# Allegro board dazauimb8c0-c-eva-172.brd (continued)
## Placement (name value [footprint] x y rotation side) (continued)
D25  *PESD5V0H1BSF  [D-0_6X0_3-0_32H-SMT]  16.57 81.12 270 bottom
D26  *PESD5V0H1BSF  [D-0_6X0_3-0_32H-SMT]  16.57 79.82 90 bottom
D27  *PESD5V0H1BSF  [D-0_6X0_3-0_32H-SMT]  17.74 79.31 270 bottom
D28  *PESD5V0H1BSF  [D-0_6X0_3-0_32H-SMT]  17.74 78.01 90 bottom
D29  *PESD5V0H1BSF  [D-0_6X0_3-0_32H-SMT]  16.57 77.41 270 bottom
D30  *PESD5V0H1BSF  [D-0_6X0_3-0_32H-SMT]  16.57 76.11 90 bottom
D31  *PESD5V0H1BSF  [D-0_6X0_3-0_32H-SMT]  17.74 76.08 270 bottom
D32  *PESD5V0H1BSF  [D-0_6X0_3-0_32H-SMT]  17.74 74.78 90 bottom
D33  RB500V-40  [D-1_85X1_25-2P-0_95H]  103.85 54.09 180 bottom
D34  1N4148WS  [D-SOD323-1_85X1_25-0_95H]  193.2 33.41 270 bottom
D35  1N4148WS  [D-SOD323-1_85X1_25-0_95H]  194.7 33.41 270 bottom
D36  RB500V-40  [D-SOD323-1_85X1_25-0_95H]  201.86 25.16 0 bottom
D37  *RB500V-40  [D-SOD323-1_85X1_25-0_95H]  200.98 23.13 0 bottom
D38  TPC@EGA10402V05AH_0.2p  [R0402]  9.97 18.78 90 bottom
D39  TPC@EGA10402V05AH_0.2p  [R0402]  11.36 18.4 0 bottom
D40  TPC@P4SMAFJ20A  [D-3_8X2_5]  15.1 14.46 270 bottom
D41  TPC@EGA10402V05AH_0.2p  [R0402]  11.62 13.83 0 bottom
D42  BAT54CW  [SOT23-1_7-65-3P]  17.26 9.88 0 bottom
D43  *RB500V-40  [D-1_85X1_25-2P-0_95H]  110.83 48.09 270 bottom
EC1  180p/25V_2  [C0201]  55.43 87.87 0 top
EC2  180p/25V_2  [C0201]  50.73 51.04 180 top
EC3  SSD@10u/6.3V_4  [C0402_2]  22.29 6.97 0 top
EC4  SSD@10u/6.3V_4  [C0402_2]  24.83 5.45 0 top
EC5  SSD@0.1u/16V_2  [C0201]  24.83 4.43 180 top
EC6  PBA@AZ5725-01F.R7G  [ESD-1X0_6-2P]  57.08 22.52 0 bottom
EC7  PBA@AZ5725-01F.R7G  [ESD-1X0_6-2P]  59.02 22.52 0 bottom
EC8  TPC@22u/6.3V_6  [C0603]  11.24 21.63 270 bottom
EC9  *220p/50V_4  [C0402]  180.48 20.1 90 bottom
FAN1  50278-00401-001  [WTB-50278-00401-V01-4P-L]  174.73 29.5 90 bottom
HD1  51625-01201-001  [51625-01201-001-12P-L]  217.53 13.57 270 bottom
HE1  APX8132AI-TRG  [SOT23-2_38-95-3P]  34.9 122.75 90 top
HOLE1  *spad-davidoff-1  [SPAD-DAVIDOFF-1]  43.94 123.9 0 top
HOLE2  *h-c98d98n  [2D-BARCODE-6X6-S]  18.76 109.23 0 top
HOLE3  *h-s157d157n  [H-S157D157N]  110.17 72.38 0 top
HOLE4  *spad-c315np  [SPAD-C315NP]  131.79 64.66 0 top
HOLE5  *spad-re209x315np  [SPAD-RE209X315NP]  215.74 37.1 0 top
HOLE6  *spad-c354np  [SPAD-C354NP]  140.49 22.1 0 top
HOLE7  *spad-c354np  [SPAD-C354NP]  41.2 10 0 top
HOLE8  *H-DAVIDOFF-3  [H-DAVIDOFF-3]  136.2 123.5 180 bottom
HOLE9  *h-c98d98n  [H-C98D98N]  142.5 123.5 180 bottom
HOLE10  EV@H-C256I186D102P2  [H-C256I186D102P2]  90.53 123.23 180 bottom
HOLE11  *hg-o335x315d252x232p2  [HG-O335X315D252X232P2]  11.25 109.2 180 bottom
HOLE12  *SPAD-RE138X197  [SPAD-RE138X197]  3.35 108.2 180 bottom
HOLE13  *h-s157d157n  [2D-BARCODE-6X6-S]  18.02 104.15 0 bottom
HOLE14  *h-tic157bc276d150p2  [H-TIC157BC276D150P2]  71.88 89.73 180 bottom
HOLE15  EV@H-C256I186D102P2  [H-C256I186D102P2]  119.53 84.23 180 bottom
HOLE16  *hg-c354i158d118p2  [HG-C354I158D118P2]  17.48 68.15 180 bottom
HOLE17  *h-tic157bc276d150p2  [H-TIC157BC276D150P2]  106.88 58.74 180 bottom
HOLE18  *HG-C276D126P2  [HG-C276D126P2]  216.55 54 180 bottom
HOLE19  *h-tic157bc276d150p2  [H-TIC157BC276D150P2]  71.88 27.73 180 bottom
HOLE20  *h-c75d75n  [H-C75D75N]  4.2 24 180 bottom
HOLE21  h-davidoff-1  [H-DAVIDOFF-1]  216.8 21.88 180 bottom
HOLE22  *hg-c354i274d220p2  [HG-C354I274D220P2]  86.2 15.5 180 bottom
HOLE23  *H-DAVIDOFF-1-1  [H-DAVIDOFF-1-1]  5.2 4.4 180 bottom
J1  *JUMP  [JOPEN25X30_S]  12 10.02 180 bottom
JDIM1  D4AS0-26010-1P40  [DDR4-D4AR0-26001-1P40-RVS-SMT]  54.35 62.83 270 bottom
L1  EV@HCB1005KF-330T30  [R0402]  88.07 107.3 180 top
L2  EV@HCB1005KF-330T30  [R0402]  88.07 106.29 180 top
L3  *EV@HCB1608KF_300_2A  [R0603]  89.44 102.14 180 top
L4  EV@HCB1005KF-330T30  [R0402]  89.85 100.93 180 top
L5  EV@HCB1005KF-330T30  [R0402]  105.6 99.43 0 top
L6  BLM15AG121SN1D  [R0402]  185.35 32.24 180 top
L7  HCB2012KF-220T60  [R0805]  202.75 31.79 0 top
L8  *Short_0603  [S0603]  49.08 31.43 180 top
L9  BLM15AG121SN1D  [R0402]  200.9 21.04 180 top
L10  BLM15AG121SN1D  [R0402]  202.58 19.75 90 top
L11  BLM15AG601SN1D  [R0402]  41.34 103.62 90 bottom
L12  BLM15AG601SN1D  [R0402]  42.48 103.62 90 bottom
L13  HCB1608KF-121T30  [R0603]  210.73 34.25 0 bottom
L14  PBY160808T-600Y-N  [R0603]  210.93 27.98 0 bottom
L15  HCB1005KF-330T30  [R0402]  72.22 22.34 90 bottom
L16  HCB1005KF-330T30  [R0402]  75.53 22.34 90 bottom
NOREF  -  []  -292.8 -269 0 top
NOREF#2  -  [unnamed#2]  217.23 12.03 0 top
NOREF#3  -  [unnamed#2]  127.37 119.82 0 top
NOREF#4  -  [unnamed#2]  10.3 23 0 top
NOREF#5  -  []  166.94 -30.24 0 top
NOREF#6  -  []  -292.8 -269 0 top
NOREF#7  -  []  107.12 22.34 0 top
NOREF#8  -  []  1.84 -42.94 0 top
NOREF#9  -  [unnamed#2]  119.72 125.46 180 bottom
NOREF#10  -  []  14.67 116.11 180 bottom
NOREF#11  -  [unnamed#2]  212.15 18.58 180 bottom
NOREF#12  -  [unnamed#2]  9.71 9.03 180 bottom
PC1  1u/10V_4  [C0402]  64.04 124.57 90 top
PC2  10u/10V_4  [C0402_2]  65.11 124.57 270 top
PC3  0.1u/25V_4  [C0402]  66.18 124.57 270 top
PC4  *EV@10u/25V_8  [C0805]  74.06 124.55 180 top
PC5  EV@10u/25V_6  [C0603]  74.06 122.52 180 top
PC6  0.047u/50V_6  [C0603]  45.86 122.13 0 top
PC7  *22u/6.3V_6  [C0603]  49.55 122.11 0 top
PC8  1000p/50V_4  [C0402]  44.05 121.73 90 top
PC9  EV@470u/2V_7343H1.9  [CC7343]  80.48 121.42 180 top
PC10  0.1u/25V_4  [C0402]  68.18 121.19 270 top
PC11  10u/25V_6  [C0603]  69.4 120.94 270 top
PC12  10u/25V_6  [C0603]  70.83 124.45 0 top
PC13  EV@10u/25V_6  [C0603]  74.06 120.49 180 top
PC14  2200p/50V_4  [C0402]  12.41 118.43 90 top
PC15  0.47u/10V_4  [C0402]  66.22 118.3 0 top
PC16  10u/6.3V_4  [C0402_2]  61.77 118.15 180 top
PC17  *EV@2200p/50V_4  [C0402]  75.25 118.1 0 top
PC18  10u/6.3V_4  [C0402_2]  63.5 118.09 180 top
PC19  EV@1u/25V_4  [C0402]  68.36 115.35 270 top
PC20  EV@0.22u/10V_4  [C0402]  73.24 115.43 270 top
PC21  EV@0.1u/16V_4  [C0402]  69.56 114.13 270 top
PC22  EV@1500p/50V_4  [C0402]  70.52 113.73 270 top
PC23  EV@0.22u/25V_4  [C0402]  77.61 113.55 270 top
PC24  EV@56p/50V_4  [C0402]  69.23 110.93 0 top
PC25  EV@2.2u/10V_4  [C0402]  78.57 110.91 270 top
PC26  *EV@100p/50V_4  [C0402]  70.65 110.45 270 top
PC27  EV@56p/50V_4  [C0402]  69.23 109.97 0 top
PC28  EV@0.22u/25V_4  [C0402]  77.91 108.44 90 top
PC29  *EV@0.22u/10V_4  [C0402]  72.07 106.67 270 top
PC30  *EV@2200p/50V_4  [C0402]  82.87 106.59 0 top
PC31  EV@10u/6.3V_6  [C0603]  20.64 97.9 0 top
PC32  EV@0.1u/16V_4  [C0402]  20.76 96.63 0 top
PC33  EV@1000p/50V_4  [C0402]  22.54 96.63 270 top
PC34  EV@1000p/50V_4  [C0402]  23.56 96.63 270 top
PC35  EV@10u/6.3V_6  [C0603]  25.59 95.11 180 top
PC36  EV@0.1u/16V_4  [C0402]  25.33 93.84 180 top
PC37  EV@1u/25V_4  [C0402]  25.72 91.3 180 top
PC38  EV@1u/25V_4  [C0402]  21.14 90.16 90 top
PC39  *EV@820p/50V_4  [C0402]  22.16 90.16 90 top
PC40  EV@0.1u/16V_4  [C0402]  23.18 90.16 90 top
PC41  EV@0.1u/16V_4  [C0402]  24.19 90.16 90 top
PC42  *EV@22u/6.3V_6  [C0603]  138.82 77.58 0 top
PC43  EV@0.1u/16V_4  [C0402]  138.01 74.38 90 top
PC44  EV@22u/6.3V_6  [C0603]  140.65 74.38 90 top
PC45  EV@22u/6.3V_6  [C0603]  142.1 74.38 90 top
PC46  EV@22u/6.3V_6  [C0603]  139.23 74.36 90 top
PC47  *EV@0.1u/25V_4  [C0402]  138.87 67.3 180 top
PC48  EV@2200p/50V_4  [C0402]  139.84 64.04 180 top
PC49  0.1u/25V_4  [C0402]  142.31 59.83 180 top
PC50  *22u/6.3V_6  [C0603]  90.38 59.4 0 top
PC51  0.1u/25V_4  [C0402]  139.3 58.7 90 top
PC52  22u/6.3V_6  [C0603]  90.38 57.97 0 top
PC53  330p/50V_4  [C0402]  143.87 56.73 0 top
PC54  22u/6.3V_6  [C0603]  90.56 56.55 0 top
PC55  0.1u/25V_4  [C0402]  134.67 55.49 270 top
PC56  82p/50V_4  [C0402]  143.55 55.37 90 top
PC57  *100p/50V_4  [C0402]  143.55 53.65 90 top
PC58  2.2u/10V_4  [C0402]  134.29 53.12 0 top
PC59  0.1u/25V_4  [C0402]  134.69 51.45 90 top
PC60  0.47u/6.3V_4  [C0402]  144.84 50.28 270 top
PC61  4.7u/6.3V_4  [C0402_2]  143.57 50.15 90 top
PC62  *0.1u/25V_4  [C0402]  138.34 40.82 90 top
PC63  22u/6.3V_6  [C0603]  113.42 38.85 0 top
PC64  22u/6.3V_6  [C0603]  113.42 37.43 0 top
PC65  *22u/6.3V_6  [C0603]  113.42 36 0 top
PC66  22u/6.3V_6  [C0603]  156.48 35.98 270 top
PC67  *22u/6.3V_6  [C0603]  157.9 35.95 270 top
PC68  2200p/50V_4  [C0402]  24.37 35.55 90 top
PC69  *22u/6.3V_6  [C0603]  159.95 35.42 180 top
PC70  10p/50V_4  [C0402]  147.56 35.34 90 top
PC71  0.1u/16V_4  [C0402]  144.84 34.53 180 top
PC72  0.1u/16V_4  [C0402]  157.67 33.92 180 top
PC73  100p/50V_4  [C0402]  138.49 33.51 0 top
PC74  0.1u/50V_4  [C0402]  132.12 32.55 90 top
PC75  *2200p/50V_6  [C0603]  37.15 32.24 270 top
PC76  0.1u/50V_4  [C0402]  133.46 32.14 0 top
PC77  *100p/50V_4  [C0402]  136.84 31.74 180 top
PC78  0.1u/16V_4  [C0402]  18.98 31.71 270 top
PC79  0.1u/16V_4  [C0402]  144.71 31.41 270 top
PC80  2.2u/10V_4  [C0402]  131.61 31.18 180 top
PC81  10u/6.3V_6  [C0603]  20.79 30.92 180 top
PC82  1u/25V_4  [C0402]  22.59 30.75 270 top
PC83  22u/6.3V_6  [C0603]  33.72 30.47 270 top
PC84  *22u/6.3V_6  [C0603]  35.27 30.47 270 top
PC85  10u/6.3V_4  [C0402_2]  44.38 29.2 180 top
PC86  2200p/50V_4  [C0402]  121.6 29.2 90 top
PC87  *0.1u/16V_4  [C0402]  25.23 28.56 180 top
PC88  1u/25V_4  [C0402]  158.05 28.23 180 top
PC89  0.01u/50V_4  [C0402]  44.38 28.05 180 top
PC90  1u/25V_4  [C0402]  152.67 27.82 90 top
PC91  *0.01u/50V_4  [C0402]  120.46 27.8 270 top
PC92  1000p/50V_4  [C0402]  19.37 27.75 0 top
PC93  0.1u/16V_4  [C0402]  25.23 27.6 180 top
PC94  *0.1u/6.3V_2  [C0201]  39.18 27.55 0 top
PC95  0.1u/6.3V_2  [C0201]  37.02 27.42 270 top
PC96  0.01u/50V_4  [C0402]  133.68 27.29 90 top
PC97  22u/6.3V_6  [C0603]  35.11 26.91 90 top
PC98  1000p/50V_4  [C0402]  19.37 26.76 0 top
PC99  *0.1u/16V_4  [C0402]  25.23 26.63 180 top
PC100  *22p/50V_4  [C0402]  39.18 25.92 270 top
PC101  1u/25V_4  [C0402]  25.23 25.67 180 top
PC102  *22p/50V_4  [C0402]  159.35 25.65 90 top
PC103  0.1u/16V_4  [C0402]  22.03 25.01 180 top
PC104  0.47u/6.3V_4  [C0402]  166.64 23.89 270 top
PC105  10u/6.3V_6  [C0603]  22.06 23.79 180 top
PC106  10u/6.3V_6  [C0603]  157.8 23.05 90 top
PC107  10u/6.3V_6  [C0603]  167.83 23 90 top
PC108  0.1u/16V_4  [C0402]  156.42 22.67 90 top
PC109  0.1u/16V_4  [C0402]  153.45 22.64 90 top
PC110  1000p/50V_4  [C0402]  154.42 22.64 90 top
PC111  1000p/50V_4  [C0402]  155.46 22.64 90 top
PC112  10u/6.3V_6  [C0603]  152.26 22.47 90 top
PC113  22u/6.3V_6  [C0603]  33.49 22.08 270 top
PC114  *22u/6.3V_6  [C0603]  34.96 22.06 270 top
PC115  *680p/50V_6  [C0603]  42.73 20.56 180 top
PC116  0.1u/25V_4  [C0402]  39.18 18.91 270 top
PC117  2200p/50V_4  [C0402]  100.54 17.31 90 top
PC118  0.1u/50V_4  [C0402]  101.92 17.26 90 top
PC119  22u/6.3V_6  [C0603]  34.99 15.99 90 top
PC120  *22u/6.3V_6  [C0603]  36.49 15.99 90 top
PC121  22u/6.3V_6  [C0603]  38.16 15.99 90 top
PC122  *47p/50V_4  [C0402]  107.63 15.87 270 top
PC123  *47p/50V_4  [C0402]  100.52 15.11 270 top
PC124  EV@0.1u/25V_4  [C0402]  69.44 125.46 0 bottom
PC125  *1u/10V_4  [C0402]  64.78 124.67 90 bottom
PC126  *1u/10V_4  [C0402]  67.22 124.53 90 bottom
PC127  EV@2200p/50V_4  [C0402]  69.44 124.5 0 bottom
PC128  *22u/6.3V_6  [C0603]  60.79 124.5 90 bottom
PC129  22u/6.3V_6  [C0603]  62.2 124.5 90 bottom
PC130  22u/6.3V_6  [C0603]  53.64 124.36 270 bottom
PC131  22u/6.3V_6  [C0603]  52.08 124.35 270 bottom
PC132  22u/6.3V_6  [C0603]  55.22 124.34 270 bottom
PC133  22u/6.3V_6  [C0603]  56.73 124.34 270 bottom
PC134  *EV@15u/25V_3528H1.9  [C3528]  73.47 124.07 180 bottom
PC135  EV@470u/2V_7343H1.9  [CC7343]  110.25 123.56 180 bottom
PC136  *680p/50V_6  [C0603]  63.65 122.45 180 bottom
PC137  22u/6.3V_6  [C0603]  49.55 122.11 0 bottom
PC138  2200p/50V_4  [C0402]  67.22 121.19 90 top
PC139  0.1u/25V_4  [C0402]  60.01 121.19 270 bottom
PC140  10u/25V_6  [C0603]  70.83 122.97 0 top
PC141  EV@22U/6.3V_6  [C0603]  103.72 120.59 0 bottom
PC142  *10u/6.3V_4  [C0402_2]  64 119.67 180 bottom
PC143  0.1u/50V_4  [C0402]  40.07 117.82 0 bottom
PC144  EV@22U/6.3V_6  [C0603]  87.69 117.74 180 bottom
PC145  0.1u/50V_4  [C0402]  40.07 116.85 0 bottom
PC146  EV@4700p/25V_4  [C0402]  74.48 112.66 90 bottom
PC147  *EV@56p/50V_4  [C0402]  73.37 108.62 270 bottom
PC148  EV@2200p/50V_4  [C0402]  77.51 106.01 270 bottom
PC149  EV@0.1u/25V_4  [C0402]  78.5 106.01 270 bottom
PC150  EV@470u/2V_7343H1.9  [CC7343]  86.88 104.53 270 bottom
PC151  EV@0.1u/16V_4  [C0402]  75.17 102.35 180 bottom
PC152  EV@10u/25V_8  [C0805]  79.51 101.46 90 bottom
PC153  EV@10u/25V_8  [C0805]  81.49 101.46 90 bottom
PC154  *EV@10u/25V_8  [C0805]  83.48 101.46 90 bottom
PC155  EV@10u/6.3V_6  [C0603]  69.66 100.04 0 bottom
PC156  EV@0.1u/16V_4  [C0402]  71.94 99.43 180 bottom
PC157  EV@10u/6.3V_6  [C0603]  69.66 98.61 0 bottom
PC158  *EV@0.1u/16V_4  [C0402]  75.37 95.87 90 bottom
PC159  EV@0.1u/16V_4  [C0402]  66.05 95.36 270 bottom
PC160  EV@10u/6.3V_6  [C0603]  64.86 94.25 270 bottom
PC161  EV@0.01u/50V_4  [C0402]  74.86 94.22 180 bottom
PC162  *22u/6.3V_6  [C0603]  115.14 80.61 270 bottom
PC163  330u/2.5V_7343H1.9  [CC7343]  111.94 80.22 90 bottom
PC164  *330u/2.5V_7343H1.9  [CC7343]  118.54 75.09 90 bottom
PC165  *330u/2.5V_7343H1.9  [CC7343]  123.34 75.09 90 bottom
PC166  *330u/2.5V_7343H1.9  [CC7343]  128.04 75.09 90 bottom
PC167  *EV@22u/6.3V_6  [C0603]  140.65 74.38 90 bottom
PC168  EV@22u/6.3V_6  [C0603]  142.1 74.38 90 bottom
PC169  EV@22u/6.3V_6  [C0603]  139.23 74.36 90 bottom
PC170  EV@10u/6.3V_6  [C0603]  141.59 72.07 180 bottom
PC171  EV@0.1u/25V_4  [C0402]  137.98 70.34 180 bottom
PC172  *EV@680p/50V_6  [C0603]  131.57 69.62 0 bottom
PC173  0.1u/25V_4  [C0402]  127.68 69.54 0 bottom
PC174  0.1u/25V_4  [C0402]  129.4 69.54 180 bottom
PC175  EV@0.01u/6.3V_2  [C0201]  140.98 69.46 0 bottom
PC176  *22u/6.3V_6  [C0603]  102.88 68.36 270 bottom
PC177  10u/25V_8  [C0805]  127.99 68.07 0 bottom
PC178  EV@0.22u/10V_4  [C0402]  141.87 67.96 180 bottom
PC179  22u/6.3V_6  [C0603]  104.3 66.89 270 bottom
PC180  *15u/25V_3528H1.9  [C3528]  132.44 66.32 270 bottom
PC181  *10u/25V_8  [C0805]  128.16 66.1 0 bottom
PC182  2200p/50V_4  [C0402]  130.26 65.98 90 bottom
PC183  *EV@1000p/50V_4  [C0402]  141.46 64.88 180 bottom
PC184  EV@10u/25V_6  [C0603]  135.77 62.78 0 bottom
PC185  *EV@0.01u/50V_4  [C0402]  139.69 62.11 180 bottom
PC186  0.1u/25V_4  [C0402]  140.75 60.66 270 bottom
PC187  0.1u/25V_4  [C0402]  141.71 60.66 270 bottom
PC188  *2200p/25V_2  [C0201]  124.2 58.95 180 bottom
PC189  10u/25V_8  [C0805]  128.86 58.55 0 bottom
PC190  2200p/50V_4  [C0402]  128.53 56.97 180 bottom
PC191  0.22u/25V_4  [C0402]  139.16 55.93 270 bottom
PC192  *0.1u/6.3V_2  [C0201]  138.1 55.85 90 bottom
PC193  0.1u/25V_4  [C0402]  134.75 55.59 90 bottom
PC194  *2200p/25V_2  [C0201]  124.23 55.56 180 bottom
PC195  *100p/50V_4  [C0402]  141.44 55.53 0 bottom
PC196  10u/25V_8  [C0805]  128.85 55.4 0 bottom
PC197  10u/25V_8  [C0805]  132.66 54.62 180 bottom
PC198  *100p/50V_4  [C0402]  141.44 54.57 0 bottom
PC199  *0.1u/6.3V_2  [C0201]  141.67 52.64 270 bottom
PC200  0.1u/6.3V_2  [C0201]  137.86 52.06 180 bottom
PC201  *22u/6.3V_6  [C0603]  113.66 51.44 0 bottom
PC202  *10u/25V_8  [C0805]  132.66 51.23 180 bottom
PC203  *22u/6.3V_6  [C0603]  113.65 49.95 0 bottom
PC204  10u/25V_8  [C0805]  132.88 49.26 180 bottom
PC205  0.1u/25V_4  [C0402]  132.14 47.79 180 bottom
PC206  *2200p/25V_2  [C0201]  126.54 47.78 180 bottom
PC207  10u/25V_8  [C0805]  130.28 47.35 90 bottom
PC208  22u/6.3V_6  [C0603]  112.48 46.57 270 bottom
PC209  *0.1u/16V_4  [C0402]  139.81 46.17 90 bottom
PC210  1u/6.3V_4  [C0402]  135.36 45.16 0 bottom
PC211  0.1u/25V_4  [C0402]  141.95 44.47 0 bottom
PC212  *22u/6.3V_6  [C0603]  111.94 43.27 90 bottom
PC213  2200p/50V_4  [C0402]  141.95 40.83 180 bottom
PC214  0.1u/25V_4  [C0402]  134.31 40.33 90 bottom
PC215  *10u/25V_8  [C0805]  130.87 40.03 270 bottom
PC216  10u/25V_8  [C0805]  132.84 40.03 270 bottom
PC217  27p/50V_4  [C0402]  141.09 39.47 90 bottom
PC218  330u/2.5V_7343H1.9  [CC7343]  118.11 38.17 0 bottom
PC219  *22u/6.3V_6  [C0603]  112.02 38.14 0 bottom
PC220  *470p/50V_4  [C0402]  141.44 38.11 0 bottom
PC221  2200p/50V_4  [C0402]  142.81 37.32 90 bottom
PC222  10u/25V_8  [C0805]  129.47 36.24 90 bottom
PC223  10u/25V_8  [C0805]  131.44 36.23 90 bottom
PC224  22u/6.3V_6  [C0603]  156.55 36.03 270 bottom
PC225  22u/6.3V_6  [C0603]  157.97 36.03 270 bottom
PC226  22u/6.3V_6  [C0603]  160.01 35.62 180 bottom
PC227  4.7u/6.3V_4  [C0402_2]  144.84 35.55 0 bottom
PC228  0.1u/25V_4  [C0402]  133.26 35.52 90 bottom
PC229  0.1u/25V_4  [C0402]  148.02 35.42 90 bottom
PC230  2200p/50V_4  [C0402]  120.74 35.33 180 bottom
PC231  0.1u/16V_4  [C0402]  118.32 35.3 180 bottom
PC232  0.1u/25V_4  [C0402]  122.09 34.94 90 bottom
PC233  10u/25V_8  [C0805]  140.65 34.48 0 bottom
PC234  1u/10V_4  [C0402]  144.51 34.43 0 bottom
PC235  100p/50V_4  [C0402]  137.98 33.49 0 bottom
PC236  2200p/50V_4  [C0402]  111.01 33.46 180 bottom
PC237  0.1u/50V_4  [C0402]  131.99 33.21 0 bottom
PC238  0.47u/25V_6  [C0603]  129.81 33.06 0 bottom
PC239  10u/25V_6  [C0603]  140.78 32.75 0 bottom
PC240  10u/25V_8  [C0805]  127.39 32.19 90 bottom
PC241  22u/25V_8  [C0805]  111.57 31.96 180 bottom
PC242  *0.1u/16V_4  [C0402]  138.64 31.66 270 bottom
PC243  0.047u/50V_6  [C0603]  129.78 31.23 0 bottom
PC244  0.1u/25V_4  [C0402]  141.41 30.59 270 bottom
PC245  0.1u/25V_4  [C0402]  142.43 30.59 90 bottom
PC246  22u/25V_8  [C0805]  111.57 29.96 180 bottom
PC247  *680p/50V_6  [C0603]  144.71 28.84 0 bottom
PC248  0.1u/25V_4  [C0402]  129.35 28.59 180 bottom
PC249  *680p/50V_6  [C0603]  127.6 28.31 270 bottom
PC250  *0.1u/16V_4  [C0402]  153.38 27.49 90 bottom
PC251  0.1u/16V_4  [C0402]  155.31 27.49 90 bottom
PC252  *0.1u/16V_4  [C0402]  156.27 27.49 90 bottom
PC253  0.1u/25V_4  [C0402]  129.02 27.24 270 bottom
PC254  0.1u/25V_4  [C0402]  129.98 27.24 270 bottom
PC255  0.1u/16V_4  [C0402]  103.31 26.63 90 bottom
PC256  0.1u/50V_4  [C0402]  94.12 24.12 180 bottom
PC257  4.7u/6.3V_4  [C0402_2]  159.32 23.23 270 bottom
PC258  *100p/50V_4  [C0402]  94.12 23.09 0 bottom
PC259  10u/6.3V_6  [C0603]  169.99 22.72 180 bottom
PC260  0.1u/16V_4  [C0402]  168.13 22.57 90 bottom
PC261  2200p/50V_4  [C0402]  47.33 20.31 180 bottom
PC262  0.1u/25V_4  [C0402]  46.8 18.96 270 bottom
PC263  0.1u/25V_4  [C0402]  47.79 18.96 90 bottom
PC264  10u/25V_8  [C0805]  49.26 17.94 270 bottom
PC265  1u/10V_4  [C0402]  42.91 16.17 0 bottom
PC266  4.7u/10V_4  [C0402_2]  41.34 15.91 90 bottom
PC267  0.1u/16V_4  [C0402]  42.91 15.19 0 bottom
PC268  0.1u/16V_4  [C0402]  33.46 15.1 0 bottom
PC269  22u/6.3V_6  [C0603]  35.88 15.1 180 bottom
PC270  10u/25V_8  [C0805]  50.68 14.26 90 bottom
PC271  0.1u/16V_4  [C0402]  46.67 14.21 180 bottom
PC272  10p/50V_4  [C0402]  44.38 13.37 180 bottom
PD1  *EV@RB500V-40  [D-SOD323-1_85X1_25-0_95H]  76.64 115.66 180 top
PD2  P4SMAFJ20A  [D-3_8X2_5]  16.06 115.3 180 top
PD3  BAT54CW  [SOT23-1_7-65-3P]  109.59 40.6 270 top
PD4  BAT54CW  [SOT23-1_7-65-3P]  126.76 31.84 180 top
PD5  PDZ5.6B  [D-SOD323-1_7X1_25-PMEG4005AEA]  109.03 16.58 90 top
PD6  PDZ5.6B  [D-SOD323-1_7X1_25-PMEG4005AEA]  99.25 15.82 90 top
PD7  EV@1SS355  [D-SOD323-1_85X1_25-0_95H]  73.09 96.13 90 bottom
PJ2  *short3720  [SHORT3720]  154.37 31.1 180 top
PJ3  *short3720  [SHORT3720]  31.05 29.96 270 top
PJ4  *short3720  [SHORT3720]  32.45 18.53 90 top
PJ6  30706-00042-001  [DCJK-30706-00042-001-3P-SMT]  1.85 116.6 90 bottom
PJ7  *short3720  [SHORT3720]  70.39 102.98 270 bottom
PJ8  *short3720  [SHORT3720]  140.65 78.6 180 bottom
PJ10  *short3720  [SHORT3720]  135.62 37.3 270 bottom
PJ11  50458-00801-V02  [WTB-50458-00801-V02-8P-L]  102.45 16.42 180 bottom
PL1  4.7uH/1.08A_2.5x2.0x1.2  [L2_5X2-1_2]  61.86 124.65 180 top
PL2  0.68uH/15.5A_7x7x3  [L6_6X6_6-2_8H]  55.56 122.37 180 top
PL3  1uH/3.35A_2.5x2.0x1.2  [L2_5X2-1_2H]  37.6 29.58 180 top
PL4  EV@0.22uH/23A_7x7x3  [L6_6X6_6-3H]  81.55 120.31 0 bottom
PL5  EV@0.22uH/23A_7x7x3  [L6_6X6_6-3H]  84.62 113.19 0 bottom
PL6  EV@0.68uH/15.5A_7x7x3  [L6_6X6_6-3H]  134.96 74.43 90 bottom
PL7  0.24uH/28A_7x7x3  [L6_6X6_6-2_8H]  119.31 62.97 180 bottom
PL8  0.24uH/28A_7x7x3  [L6_6X6_6-2_8H]  119.84 51.52 180 bottom
PL9  0.22uH/23A_7x7x3  [L6_6X6_6-2_8H]  117.86 44.22 180 bottom
PL10  1uH/11A_7x7x3  [L6_6X6_6-2_8H]  152.21 32.12 0 bottom
PL11  6.8uH/4.5A_7x7x3  [L6_6X6_6-2_8H]  117.82 29.07 180 bottom
PL12  2.2uH/1.67A_2.5x2.0x1.2  [L2_5X2-1_2H]  166.05 22.97 0 bottom
PL13  1uH/11A_7x7x3  [L6_6X6_6-2_8H]  37.07 19.42 180 bottom
PQ1  EV@LTC044EUBFS8TL  [SOT23-1_7-65-3P]  122.87 122.8 0 top
PQ2  EV@2N7002KW  [SOT23-1_7-65-3P]  123.76 119.87 90 top
PQ3  AONS32314  [POWER-5_2X5_55-1_27-5P]  40.12 119.49 0 top
PQ4  AONS32314  [POWER-5_2X5_55-1_27-5P]  46.98 118.05 180 top
PQ5  EV@2N7002K  [SOT23-2-95-3P]  135.8 77.91 180 top
PQ6  EV@DMG1012T-7  [SOT23-1_38-5-3P]  131.91 77.13 270 top
PQ7  DDTC144EUA-7-F  [SOT23-1_7-65-3P]  24.57 40.47 90 top
PQ8  2N7002K  [SOT23-2-95-3P]  27.49 37.63 90 top
PQ9  2N7002KW  [SOT23-1_7-65-3P]  136.92 35.43 180 top
PQ10  AOSS32334C  [SOT23-2_38-95-3P]  26.76 34.15 180 top
PQ11  AONS32314  [POWER-5_2X5_55-1_27-5P]  116.98 30.59 270 top
PQ12  2N7002K  [SOT23-2-95-3P]  142.3 29.32 270 top
PQ13  2N7002K  [SOT23-2-95-3P]  46.65 14.97 180 top
PQ14  EV@AOE6936  [POWER-5X6-1_27-10P]  73.77 119.19 90 bottom
PQ15  EV@2N7002K  [SOT23-2-95-3P]  71.05 106.97 0 bottom
PQ16  EV@AOE6936  [POWER-5X6-1_27-10P]  81.77 106.39 180 bottom
PQ17  EV@2N7002K  [SOT23-2-95-3P]  74.51 104.68 270 bottom
PQ18  EV@DMG1012T-7  [SOT23-1_38-5-3P]  77.38 103.87 270 bottom
PQ19  EV@AON7408  [DFN-8L-3X3-65-5P-0_9H]  69.71 96 0 bottom
PQ20  AOE6936  [POWER-5X6-1_27-10P]  127.46 62.39 270 bottom
PQ21  AOE6936  [POWER-5X6-1_27-10P]  127.77 51.67 270 bottom
PQ22  AON6354  [POWER-5_2X5_55-1_27-5P]  125.89 44.44 0 bottom
PQ23  *2N7002K  [SOT23-2-95-3P]  19.49 38.59 90 bottom
PQ24  AONS36380  [POWER-5_2X5_55-1_27-5P]  125.67 38.24 90 bottom
PQ25  2N7002K  [SOT23-2-95-3P]  19.49 35.22 90 bottom
PQ26  AON7410  [DFN-8L-3X3-65-5P-0_9H]  124.32 32.85 270 bottom
PQ27  AON7410  [DFN-8L-3X3-65-5P-0_9H]  124.65 28.94 0 bottom
PQ28  *2N7002K  [SOT23-2-95-3P]  19.11 28.56 90 bottom
PR1  EV@1M_5%_6  [R0603]  119.95 125.21 180 top
PR2  *short_4  [S0402]  67.54 124.81 180 top
PR3  EV@1M_5%_6  [R0603]  119.95 123.79 0 top
PR4  *EV@100K_1%_6  [R0603]  125.79 122.41 270 top
PR5  EV@22_5%_8  [R0805]  120.33 120.38 180 top
PR6  *Short_6  [S0603]  60.52 119.46 180 top
PR7  *Short_2  [S0201]  60.26 118.35 0 top
PR8  *Short_2  [S0201]  64.75 118.31 90 top
PR9  *short_4  [S0402]  68.24 118.3 180 top
PR10  *EV@2.2_5%_6  [R0603]  77.53 117.97 180 top
PR11  *EV@1K_1%_4  [R0402]  75.25 117.08 180 top
PR12  0.01_1%_0612  [RC3216]  51.95 116.9 90 top
PR13  *short_4  [S0402]  70.04 115.86 270 top
PR14  *EV@12K_1%_4  [R0402]  71.31 115.76 270 top
PR15  *EV@10K_1%_4  [R0402]  72.27 115.76 90 top
PR16  EV@1_5%_6  [R0603]  66.18 115.66 180 top
PR17  *short_4  [S0402]  74.23 115.43 90 top
PR18  *Short_2  [S0201]  51.62 114.49 270 top
PR19  *Short_2  [S0201]  52.39 114.49 270 top
PR20  *Short_2  [S0201]  71.51 114.16 0 top
PR21  EV@499K_1%_4  [R0402]  67.14 114.08 270 top
PR22  *Short_2  [S0201]  71.51 113.45 180 top
PR23  EV@100_1%_2  [R0201]  68.44 112.76 0 top
PR24  *Short_2  [S0201]  69.23 111.82 180 top
PR25  *Short_2  [S0201]  77.58 111.07 0 top
PR26  *Short_2  [S0201]  69.66 109.08 0 top
PR27  *EV@2.2_5%_6  [R0603]  83.25 108.44 270 top
PR28  EV@100_1%_2  [R0201]  70.05 108.22 180 top
PR29  *Short_2  [S0201]  74.36 107.56 180 top
PR30  *EV@0_5%_2  [R0201]  70.93 107.38 0 top
PR31  EV@10K_1%_4  [R0402]  73.09 106.51 90 top
PR32  EV@10K_1%_2  [R0201]  74.1 105.9 180 top
PR33  EV@1_5%_6  [R0603]  78.29 105.9 180 top
PR34  *Short_8  [S0805]  21.65 101.08 45 top
PR35  *Short_8  [S0805]  25.72 97.01 180 top
PR36  *Short_0402  [S0402]  22.16 87.87 270 top
PR37  *Short_0402  [S0402]  23.18 87.87 270 top
PR38  *Short_0402  [S0402]  24.19 87.87 90 top
PR39  EV@22_5%_8  [R0805]  139.28 79.31 0 top
PR40  EV@100K_1%_4  [R0402]  133.23 79.06 180 top
PR41  *Short_2  [S0201]  140.7 77.71 0 top
PR42  EV@1M_5%_2  [R0201]  133.54 77.62 270 top
PR43  *EV@0_5%_2  [R0201]  140.85 67.93 180 top
PR44  *Short_2  [S0201]  141.84 67.88 0 top
PR45  *short_4  [S0402]  139.86 65.9 270 top
PR46  *Short_2  [S0201]  142.12 60.72 180 top
PR47  10_1%_2  [R0201]  140.55 60.21 180 top
PR48  3.83K_1%_4  [R0402]  138.34 58.7 270 top
PR49  680_1%_2  [R0201]  140.26 58.55 270 top
PR50  680_1%_2  [R0201]  141.54 58.48 270 top
PR51  3.83K_1%_4  [R0402]  142.5 58.48 270 top
PR52  110K_1%_2  [R0201]  137.37 58.33 90 top
PR53  *Short_2  [S0201]  135.37 58.32 0 top
PR54  10K_1%_4  [R0402]  143.78 58.07 270 top
PR55  10K_1%_2  [R0201]  135.24 57.44 90 top
PR56  21.5K_1%_4  [R0402]  144.51 55.37 270 top
PR57  3.9_5%_4  [R0402]  144.84 52.18 90 top
PR58  15.8K_1%_4  [R0402]  143.55 51.93 270 top
PR59  *100K_1%_6  [R0603]  26.22 51.24 270 top
PR60  *Short_2  [S0201]  136.72 49.28 90 top
PR61  *Short_2  [S0201]  137.46 49.28 90 top
PR62  *Short_2  [S0201]  138.2 49.28 90 top
PR63  *Short_2  [S0201]  138.93 49.28 90 top
PR64  1M_5%_6  [R0603]  28.05 41.26 90 top
PR65  100K_1%_4  [R0402]  137.38 40.82 90 top
PR66  100K_1%_4  [R0402]  139.69 40.77 90 top
PR67  1M_5%_6  [R0603]  26.63 40.6 90 top
PR68  *Short_6  [S0603]  144.84 37.6 180 top
PR69  1M_5%_6  [R0603]  132.29 36.26 180 top
PR70  10K_1%_4  [R0402]  145.15 35.9 180 top
PR71  1M_5%_6  [R0603]  130.24 35.42 270 top
PR72  1K_1%_4  [R0402]  146.57 35.34 90 top
PR73  1M_5%_6  [R0603]  29.37 34.58 90 top
PR74  100K_1%_4  [R0402]  133.74 33.87 270 top
PR75  100K_1%_4  [R0402]  134.71 33.87 90 top
PR76  SP@20.5K_1%_4  [R0402]  136.71 32.88 0 top
PR77  *Short_2  [S0201]  144.26 32.88 90 top
PR78  *1K_1%_4  [R0402]  145.83 32.88 0 top
PR79  *2.2_5%_6  [R0603]  38.72 32.24 270 top
PR80  *Short_2  [S0201]  134.83 32.24 0 top
PR81  20_5%_12  [R1206]  129.4 31.48 270 top
PR82  *100K_1%_4  [R0402]  141.46 31.48 0 top
PR83  10K_1%_4  [R0402]  143.75 31.41 270 top
PR84  *10K_1%_4  [R0402]  146.7 31.41 270 top
PR85  100K_5%_4  [R0402]  136.84 30.72 0 top
PR86  *0_5%_2  [R0201]  136.74 29.73 270 top
PR87  *Short_8  [S0805]  18.73 29.22 0 top
PR88  *Short_2  [S0201]  136.74 28.74 90 top
PR89  *Short_2  [S0201]  27.21 28.56 180 top
PR90  1M_5%_2  [R0201]  137.82 28.05 0 top
PR91  *Short_2  [S0201]  42.05 27.67 90 top
PR92  *0_5%_2  [R0201]  140.27 27.67 180 top
PR93  *Short_2  [S0201]  27.21 27.6 0 top
PR94  *Short_2  [S0201]  38.03 27.55 180 top
PR95  *Short_2  [S0201]  36.26 27.42 90 top
PR96  *Short_2  [S0201]  141.82 27.3 0 top
PR97  100K_1%_4  [R0402]  132.71 27.29 270 top
PR98  316K_1%_4  [R0402]  135.06 27.29 180 top
PR99  *Short_6  [S0603]  130.87 27.16 180 top
PR100  *short_4  [S0402]  27.47 26.63 0 top
PR101  100K_1%_2  [R0201]  42.05 26.53 90 top
PR102  *100K_1%_2  [R0201]  168.03 26.3 270 top
PR103  20K_1%_2  [R0201]  40.14 25.92 90 top
PR104  10K_1%_4  [R0402]  41.11 25.92 270 top
PR105  15K_1%_2  [R0201]  158.18 25.73 90 top
PR106  22.6K_1%_4  [R0402]  160.36 25.65 270 top
PR107  *Short_8  [S0805]  151.45 25.39 0 top
PR108  10_1%_6  [R0603]  130.87 25.13 180 top
PR109  *Short_2  [S0201]  167.73 25.01 180 top
PR110  *Short_8  [S0805]  160.13 23.56 0 top
PR111  *Short_8  [S0805]  18.3 23.46 180 top
PR112  *0_5%_2  [R0201]  99.25 20.94 180 top
PR113  100_5%_2  [R0201]  101.28 20.94 180 top
PR114  *4.7_5%_6  [R0603]  40.07 20.56 180 top
PR115  10_1%_6  [R0603]  41.08 19.04 180 top
PR116  *short_4  [S0402]  167.45 18.15 180 top
PR117  *Short_6  [S0603]  42.48 15.99 90 top
PR118  *100K_1%_4  [R0402]  44.12 15.86 0 top
PR119  100_5%_2  [R0201]  106.11 15.69 270 top
PR120  100_5%_2  [R0201]  101.87 14.72 180 top
PR121  *0_5%_2  [R0201]  47.05 11.42 0 top
PR122  *Short_2  [S0201]  47.05 10.65 0 top
PR123  *Short_2  [S0201]  63.72 125.46 270 bottom
PR124  *Short_2  [S0201]  65.62 124.88 270 bottom
PR125  *Short_2  [S0201]  68.07 124.58 270 bottom
PR126  *0_5%_2  [R0201]  65.76 124.02 180 bottom
PR127  *Short_8  [S0805]  58.77 123.78 90 bottom
PR128  *Short_2  [S0201]  67.27 121.04 90 bottom
PR129  *4.7_5%_6  [R0603]  61.81 121.02 180 bottom
PR130  *Short_6  [S0603]  64.45 120.98 180 bottom
PR131  100K_1%_4  [R0402]  66.35 120.01 90 bottom
PR132  5.1_1%_6  [R0603]  60.77 119.52 180 bottom
PR133  100K_NTC_4_1%  [R0402]  79.89 116.22 180 bottom
PR134  EV@14.7K_1%_4  [R0402]  74.66 115.84 0 bottom
PR135  EV@1_5%_6  [R0603]  72.43 115.68 0 bottom
PR136  EV@309_1%_4  [R0402]  70.06 115.48 90 bottom
PR137  EV@4.32K_1%_4  [R0402]  72.15 114.11 0 bottom
PR138  EV@16.5K_1%_4  [R0402]  70.24 113.73 270 bottom
PR139  EV@6.19K_1%_4  [R0402]  73.52 112.66 270 bottom
PR140  EV@20.5K_1%_4  [R0402]  71.69 112.18 180 bottom
PR141  EV@5.6_5%_8  [R0805]  69.78 110.48 270 bottom
PR142  EV@10K_1%_2  [R0201]  71.44 110.37 180 bottom
PR143  EV@1_5%_6  [R0603]  76.26 108.95 180 bottom
PR144  EV@15.4K_1%_4  [R0402]  74.33 108.6 270 bottom
PR145  EV@100K_1%_2  [R0201]  76 107.43 180 bottom
PR146  EV@1M_5%_2  [R0201]  76 106.41 0 bottom
PR147  *Short_0201  [S0201]  76.39 102.09 90 bottom
PR148  EV@10K_1%_2  [R0201]  77.15 102.09 270 bottom
PR149  EV@133_1%_4  [R0402]  72.68 101.81 90 bottom
PR150  EV@124_1%_4  [R0402]  73.34 99.81 270 bottom
PR151  EV@10K_1%_4  [R0402]  73.21 98.41 180 bottom
PR152  EV@47_1%_4  [R0402]  74.36 95.87 90 bottom
PR153  *Short_0402  [S0402]  76.39 95.87 90 bottom
PR154  EV@2.2_5%_6  [R0603]  139.56 71.36 90 bottom
PR155  EV@10_5%_6  [R0603]  141.59 70.62 0 bottom
PR156  *EV@4.7_5%_6  [R0603]  134.2 69.62 0 bottom
PR157  *Short_2  [S0201]  141.9 69.28 90 bottom
PR158  EV@100K_1%_2  [R0201]  142.61 69.28 90 bottom
PR159  100_1%_2  [R0201]  121.25 68.96 0 bottom
PR160  100K_NTC_4_1%  [R0402]  124.99 67.15 90 bottom
PR161  100K_NTC_4_1%  [R0402]  123.82 67.14 90 bottom
PR162  100_1%_2  [R0201]  122.49 67.04 90 bottom
PR163  EV@2.2K_5%_2  [R0201]  141.87 66.99 0 bottom
PR164  *Short_2  [S0201]  120.19 66.88 0 bottom
PR165  *Short_2  [S0201]  121.17 66.88 0 bottom
PR166  *EV@0_5%_4  [R0402]  141.95 66.03 0 bottom
PR167  EV@6.49K_1%_4  [R0402]  141.46 63.89 0 bottom
PR168  EV@100K_1%_4  [R0402]  140.07 63.49 90 bottom
PR169  EV@9.31K_1%_2  [R0201]  141.49 62.88 0 bottom
PR170  1_5%_6  [R0603]  131.42 62.38 270 bottom
PR171  3.32K_1%_4  [R0402]  142.26 59.23 180 bottom
PR172  2.2_5%_6  [R0603]  139.14 58.75 90 bottom
PR173  *2.2_5%_6  [R0603]  122.39 58.64 0 bottom
PR174  2.43K_1%_4  [R0402]  140.35 58.45 270 bottom
PR175  3.32K_1%_4  [R0402]  141.97 58.24 0 bottom
PR176  2.43K_1%_4  [R0402]  142.35 56.89 270 bottom
PR177  40.2K_1%_2  [R0201]  140.36 56.65 180 bottom
PR178  10K_1%_2  [R0201]  143.33 56.39 180 bottom
PR179  *2.2_5%_6  [R0603]  122.4 55.83 0 bottom
PR180  402_1%_2  [R0201]  140.23 55.8 270 bottom
PR181  348_1%_2  [R0201]  142.8 55.66 180 bottom
PR182  *Short_2  [S0201]  119.91 55.6 90 bottom
PR183  *Short_2  [S0201]  120.64 55.6 90 bottom
PR184  *Short_2  [S0201]  143.37 54.94 0 bottom
PR185  *Short_2  [S0201]  143.37 54.23 0 bottom
PR186  2.2_5%_6  [R0603]  137.32 53.75 90 bottom
PR187  1_5%_6  [R0603]  132.35 52.92 0 bottom
PR188  *10K_1%_2  [R0201]  142.38 52.64 90 bottom
PR189  348_1%_2  [R0201]  140.96 52.61 270 bottom
PR190  17.4K_1%_4  [R0402]  143.57 52.18 90 bottom
PR191  6.49K_1%_4  [R0402]  144.84 52.18 90 bottom
PR192  301_1%_2  [R0201]  139.52 52.12 90 bottom
PR193  60.4_1%_2  [R0201]  140.24 52.12 90 bottom
PR194  200_1%_2  [R0201]  138.71 51.93 90 bottom
PR195  *Short_2  [S0201]  142.06 51.79 0 bottom
PR196  15K_1%_2  [R0201]  141.09 51.26 270 bottom
PR197  20K_1%_2  [R0201]  139.52 51.14 90 bottom
PR198  8.06K_1%_2  [R0201]  140.24 51.14 270 bottom
PR199  22.1K_1%_2  [R0201]  138.71 50.94 90 bottom
PR200  *short_4  [S0402]  137.85 50.85 270 bottom
PR201  9.31K_1%_2  [R0201]  139.78 49.51 0 bottom
PR202  182_1%_2  [R0201]  140.76 49.51 0 bottom
PR203  *10K_1%_2  [R0201]  136.71 49.37 90 bottom
PR204  *75_1%_2  [R0201]  137.45 49.37 270 bottom
PR205  100_1%_2  [R0201]  138.19 49.37 270 bottom
PR206  45.3_1%_2  [R0201]  138.92 49.37 270 bottom
PR207  6.2_5%_6  [R0603]  142.57 49.37 0 bottom
PR208  52.3K_1%_2  [R0201]  139.78 48.8 0 bottom
PR209  110_1%_2  [R0201]  140.76 48.8 0 bottom
PR210  *2.2_5%_6  [R0603]  124.73 47.97 0 bottom
PR211  *short_4  [S0402]  137.45 47.47 180 bottom
PR212  *100K_1%_2  [R0201]  139.07 47.46 0 bottom
PR213  *10K_1%_4  [R0402]  144.13 47.38 90 bottom
PR214  *0_5%_2  [R0201]  141.13 47.1 180 bottom
PR215  *Short_2  [S0201]  143.28 47.01 270 bottom
PR216  5.1_1%_6  [R0603]  135.88 46.97 270 bottom
PR217  100K_1%_2  [R0201]  137.82 46.63 180 bottom
PR218  100K_1%_2  [R0201]  138.8 46.63 0 bottom
PR219  *100K_1%_2  [R0201]  136.95 46.06 270 bottom
PR220  2.2_5%_6  [R0603]  141.61 45.96 0 bottom
PR221  *Short_2  [S0201]  137.8 45.92 0 bottom
PR222  *Short_2  [S0201]  138.81 45.92 180 bottom
PR223  *100K_1%_6  [R0603]  143.63 45.2 90 bottom
PR224  340K_1%_4  [R0402]  141.95 43.51 0 bottom
PR225  10K_1%_2  [R0201]  142.58 42.47 180 bottom
PR226  *short_4  [S0402]  141.57 42.17 90 bottom
PR227  *Short_2  [S0201]  142.59 41.71 180 bottom
PR228  1_5%_6  [R0603]  129.18 40.31 90 bottom
PR229  10K_1%_4  [R0402]  142.05 39.47 90 bottom
PR230  100K_1%_4  [R0402]  144.08 39.23 0 bottom
PR231  6.34K_1%_4  [R0402]  139.72 39.07 0 bottom
PR232  *22_5%_8  [R0805]  22.29 38.85 90 bottom
PR233  *short_4  [S0402]  138.38 38.69 90 bottom
PR234  10K_1%_4  [R0402]  144.33 38.21 180 bottom
PR235  *1.4K_1%_4  [R0402]  139.72 38.11 180 bottom
PR236  *Short_2  [S0201]  159.19 36.69 180 bottom
PR237  *Short_2  [S0201]  143.47 35.72 180 bottom
PR238  22_5%_8  [R0805]  22.29 35.55 90 bottom
PR239  10_1%_6  [R0603]  146.75 35.55 90 bottom
PR240  100_1%_2  [R0201]  116.29 35.42 0 bottom
PR241  100_1%_2  [R0201]  113.84 35.41 180 bottom
PR242  *Short_2  [S0201]  115.42 35.28 270 bottom
PR243  *Short_2  [S0201]  114.7 35.28 270 bottom
PR244  *Short_2  [S0201]  143.29 34.45 90 bottom
PR245  866K_1%_4  [R0402]  135.67 34.03 90 bottom
PR246  137K_1%_4  [R0402]  136.64 34.03 90 bottom
PR247  4.02K_1%_4  [R0402]  134.58 33.84 90 bottom
PR248  4.02K_1%_4  [R0402]  133.62 33.79 90 bottom
PR249  *Short_2  [S0201]  136.43 32.82 180 bottom
PR250  *Short_2  [S0201]  137.3 32.47 270 bottom
PR251  *Short_2  [S0201]  137.58 31.61 180 bottom
PR252  *100K_1%_2  [R0201]  137.6 30.9 0 bottom
PR253  *Short_2  [S0201]  138.31 30.01 180 bottom
PR254  *Short_6  [S0603]  129.78 29.81 0 bottom
PR255  *Short_2  [S0201]  138.31 29.3 180 bottom
PR256  *220_5%_8  [R0805]  21.91 29.02 90 bottom
PR257  *Short_2  [S0201]  156.4 28.87 90 bottom
PR258  *4.7_5%_6  [R0603]  146.75 28.23 90 bottom
PR259  *Short_2  [S0201]  152.36 27.95 0 bottom
PR260  *short_4  [S0402]  154.34 27.49 270 bottom
PR261  *Short_2  [S0201]  131.23 27.47 180 bottom
PR262  150_5%_4  [R0402]  101.66 27.39 180 bottom
PR263  32.4K_1%_4  [R0402]  108.52 27.32 90 bottom
PR264  10K_5%_4  [R0402]  137.27 27.16 90 bottom
PR265  *10K_5%_4  [R0402]  138.24 27.16 90 bottom
PR266  0.01_1%_0612  [RC3216]  111.57 27.01 90 bottom
PR267  *Short_2  [S0201]  131.23 26.71 180 bottom
PR268  *4.7_5%_6  [R0603]  122.69 26.2 180 bottom
PR269  *Short_2  [S0201]  108.47 25.74 0 bottom
PR270  *Short_2  [S0201]  120.43 25.13 180 bottom
PR271  *Short_2  [S0201]  120.43 24.37 180 bottom
PR272  *Short_2  [S0201]  168.03 23.93 270 bottom
PR273  *Short_2  [S0201]  46.04 16.62 270 bottom
PR274  *1K_1%_4  [R0402]  44.64 16.17 0 bottom
PR275  *10K_1%_4  [R0402]  44.64 15.2 180 bottom
PR276  *Short_2  [S0201]  47.36 15.05 0 bottom
PR277  *Short_2  [S0201]  39.56 13.7 180 bottom
PR278  1K_1%_4  [R0402]  42.61 13.42 0 bottom
PR279  10K_1%_4  [R0402]  46.92 12.81 180 bottom
PU1  TPS51486RJER  [QFN18-3X3-5]  64.27 121.04 0 top
PU2  EV@RT8813DGQW  [QFN24-4X4-5-25P-RT8813D]  73.98 110.78 180 top
PU3  EV@JW7110DFNC_TRPBF  [DFN14-3X2-4-15P-0_85H]  22.54 93.59 0 top
PU4  RT3612EBGQW-03  [QFN32-4X4-4-33P-RT8171B]  139.46 53.86 0 top
PU5  JW5213DFND_TRPBF  [DFN8-2X2-5-9P-MAX8902B]  41.24 29.63 90 top
PU6  JW7110DFNC_TRPBF  [DFN14-3X2-4-15P-0_85H]  22.26 27.42 90 top
PU7  JW7110DFNC_TRPBF  [DFN14-3X2-4-15P-0_85H]  154.85 26.73 180 top
PU8  EV@G9336ADJTP1U  [TSOT23-6-2_8-95-6P-1H]  75.88 99.17 90 bottom
PU9  EV@G5335QT2U  [QFN23-4X4-5-25P]  137.81 66.69 270 bottom
PU10  RT6543AGQW  [WQFN20-3X3-4-21P]  137.96 42.54 270 bottom
PU11  RT6256BGQUF  [QFN12-3X3-45-0_6H]  145.27 31.36 270 bottom
PU12  BQ24780SRUYR  [QFN28-4X4-4-38P]  134.22 29.91 0 bottom
PU13  TMP708AIDBVR  [SOT23-2_8-95-5P-LP2985-50DBVT]  105.9 26.33 0 bottom
PU14  JW5222RSOTB_TRPBF  [SOT23-2_8-95-6P-1_1H]  162.16 23.25 0 bottom
PU15  RT6258CGQUF  [QFN12-3X3-45-0_6H]  44 18.96 90 bottom
Q1  *EV@DMG1012T-7  [SOT23-1_38-5-3P]  98.36 123.94 180 top
Q2  AO3413  [SOT23-2_38-95-3P]  53.86 111.49 0 top
Q3  DDTC144EUA-7-F  [SOT23-1_7-65-3P]  59.24 111.44 0 top
Q4  2N7002KDW  [SOT363-2_1-65-6P]  56.58 102.48 270 top
Q5  EV@DMG1012T-7  [SOT23-1_38-5-3P]  136.21 101.08 0 top
Q6  2N7002K  [SOT23-2-95-3P]  59.49 99.55 0 top
Q7  PJA138K  [SOT23-2-95-3P]  64.07 97.5 90 top
Q8  EV@DMG1012T-7  [SOT23-1_38-5-3P]  87.69 95.41 0 top
Q9  EV@DMG1012T-7  [SOT23-1_38-5-3P]  87.69 93.2 0 top
Q10  HDMI_N@2N7002K  [SOT23-2-95-3P]  18.1 87.62 270 top
Q11  METR3904-G  [SOT23-2-95-3P]  113.85 66.79 180 top
Q12  DMG301NU-7  [SOT23-2-95-3P]  110.3 65.26 90 top
Q13  HDMI_N@SSM6N43FU  [SC70-2_1-65-6P]  24.32 63.49 90 top
Q14  *DMG3414U-7  [SOT23-2-95-3P]  47.94 33.79 270 top
Q15  EV@PJT138K  [SC70-2_1-65-6P]  173.29 31.74 180 top
Q16  METR3904-G  [SOT23-2-95-3P]  176.92 30.31 180 top
Q17  *2N7002KDW  [SOT363-2_1-65-6P]  49.21 27.67 0 top
Q18  2N7002KTB  [SOT23-1_38-5-3P]  174.28 21.02 0 top
Q19  PBA@DMP2130L-7  [SOT23-2_38-95-3P]  49.8 19.42 90 top
Q20  2N7002K  [SOT23-2-95-3P]  174.26 17.84 0 top
Q21  2N7002KDW  [SOT363-2_1-65-6P]  72.43 16.55 180 top
Q22  TPC@2N7002KDW  [SOT363-2_1-65-6P]  21.22 15.35 270 top
Q23  TPC@EMB20P03V  [POWER-3X3-65-5P]  17.94 14.85 180 top
Q24  *2N7002KDW  [SOT363-2_1-65-6P]  55.56 14.85 270 top
Q25  EV@2N7002KTB  [SOT23-1_38-5-3P]  201.08 11.21 180 top
Q26  TPC@MMBT3906-7-F  [SOT23-2-95-3P]  14.41 10.32 90 top
Q27  SSD@2N7002K  [SOT23-2-95-3P]  24.95 8.16 180 top
Q28  2N7002KTB  [SOT23-1_38-5-3P]  15.73 7.76 270 top
Q29  *2N7002KTB  [SOT23-1_38-5-3P]  17.94 7.76 270 top
Q30  TPC@2N7002K  [SOT23-2-95-3P]  12.79 5.7 270 top
Q31  EV@PJA138K  [SOT23-2-95-3P]  84.9 91.68 270 bottom
Q32  *DMG1012T-7  [SOT23-1_38-5-3P]  90.24 85.9 0 bottom
Q33  AP2331SA-7  [SOT23-2-95-3P]  19.24 81.9 180 bottom
Q34  HDMI_N@DMN601K-7  [SOT23-2-95-3P]  21.68 74.56 0 bottom
Q35  *2N7002KDW  [SOT363-2_1-65-6P]  109.92 67.93 180 bottom
Q36  DMG3414U-7  [SOT23-2-95-3P]  107.05 65.49 180 bottom
Q37  DMG3414U-7  [SOT23-2-95-3P]  111.36 64.88 0 bottom
Q38  *2N7002KDW  [SOT363-2_1-65-6P]  113.22 60.03 270 bottom
Q39  *2N7002KDW  [SOT363-2_1-65-6P]  113.22 56.17 0 bottom
Q40  *2N7002KDW  [SOT363-2_1-65-6P]  109.18 40.3 270 bottom
Q41  2N7002KDW  [SOT363-2_1-65-6P]  84.52 23.99 90 bottom
Q42  TPC@2N7002K  [SOT23-2-95-3P]  8.82 23.23 0 bottom
Q43  *BSS138BK  [SOT23-2_38-95-3P]  65.85 22.54 180 bottom
Q44  KBL@DDTC144EUA-7-F  [SOT23-1_7-65-3P]  197.05 21.17 180 bottom
Q45  *PJA138K  [SOT23-2-95-3P]  200.21 20.43 180 bottom
Q46  *2N7002KTB  [SOT23-1_38-5-3P]  180.5 17.61 0 bottom
Q47  KBL@DMP2130L-7  [SOT23-2_38-95-3P]  196.28 14.62 90 bottom
R1  *EV@Short_0402  [S0402]  102.25 124.62 180 top
R2  *EV@0_5%_4  [R0402]  100.52 124.07 180 top
R3  *EV@4.7K_5%_2  [R0201]  100.52 123.05 0 top
R4  *Short_0805  [S0805]  41.77 115.23 0 top
R5  100K_5%_4  [R0402]  57.21 112.38 90 top
R6  2.49K_1%_4  [R0402]  42.91 112.36 90 top
R7  *2.2_1%_8  [R0805]  50.94 112.13 90 top
R8  75_1%_8  [R0805]  31.68 111.62 90 top
R9  75_1%_8  [R0805]  28.76 111.52 90 top
R10  75_1%_8  [R0805]  34.73 111.37 90 top
R11  75_1%_8  [R0805]  37.53 111.37 90 top
R12  *1K_5%_2  [R0201]  62.16 111.24 270 top
R13  10K_5%_4  [R0402]  61.28 111.11 270 top
R14  10K_5%_4  [R0402]  57.21 110.6 90 top
R15  680_5%_4  [R0402]  44.77 109.84 270 top
R16  10_5%_4  [R0402]  45.78 109.84 90 top
R17  *EV@Short_0402  [S0402]  101.28 109.33 180 top
R18  *100K_1%_4  [R0402]  60.72 109.18 0 top
R19  100K_5%_4  [R0402]  58.99 108.95 180 top
R20  *short_4  [S0402]  57.64 108.83 90 top
R21  *1K_5%_2  [R0201]  54.57 108.57 0 top
R22  *100K_1%_4  [R0402]  60.72 108.06 0 top
R23  *100K_5%_4  [R0402]  51.4 107.3 90 top
R24  10K_5%_4  [R0402]  52.36 107.3 270 top
R25  10_5%_4  [R0402]  53.33 107.3 270 top
R26  1K_1%_4  [R0402]  54.29 107.3 90 top
R27  100K_1%_4  [R0402]  55.26 107.3 270 top
R28  *short_4  [S0402]  57.85 107.05 270 top
R29  EV@10K_1%_4  [R0402]  119.82 106.92 270 top
R30  15K_1%_2  [R0201]  49.59 105.07 180 top
R31  1K_5%_2  [R0201]  51.37 105.12 0 top
R32  33_5%_2  [R0201]  55.05 104.89 90 top
R33  *short_4  [S0402]  56.45 104.89 180 top
R34  *0_5%_6  [R0603]  62.37 104.81 180 top
R35  EV@1.33K_1%_2  [R0201]  132.65 104.43 0 top
R36  EV@549_1%_2  [R0201]  134.43 104.38 180 top
R37  100K_5%_4  [R0402]  66.56 103.52 90 top
R38  *Short_0603  [S0603]  62.37 103.39 0 top
R39  *Short_0402  [S0402]  58.99 103.11 270 top
R40  EV@931_1%_4  [R0402]  134.43 103.11 0 top
R41  *0_5%_6  [R0603]  60.26 102.91 270 top
R42  *EV@Short_0402  [S0402]  98.63 102.8 90 top
R43  EV@931_1%_4  [R0402]  133.92 101.08 0 top
R44  *0_5%_4  [R0402]  57.21 100.16 270 top
R45  EV@549_1%_2  [R0201]  133.92 100.11 180 top
R46  *EV@60.4_1%_2  [R0201]  110.76 100.01 270 top
R47  *0_5%_4  [R0402]  49.46 99.3 90 top
R48  24.9_1%_4  [R0402]  55.23 99.17 180 top
R49  EV@1.33K_1%_2  [R0201]  133.92 99.15 180 top
R50  EV@10K_1%_4  [R0402]  87.95 99.05 0 top
R51  2.7_5%_6  [R0603]  51.27 98.92 0 top
R52  *10K_5%_4  [R0402]  56.96 98.79 180 top
R53  *EV@Short_0402  [S0402]  89.85 98.67 180 top
R54  1.8K_1%_2  [R0201]  47.43 98.54 270 top
R55  10K_5%_4  [R0402]  61.66 98.36 90 top
R56  EV@10K_1%_4  [R0402]  87.95 98.03 0 top
R57  *0_5%_4  [R0402]  55.94 97.27 90 top
R58  *Short_0402  [S0402]  56.91 97.27 270 top
R59  *EV@60.4_1%_2  [R0201]  110.43 97.11 0 top
R60  EV@10K_1%_4  [R0402]  85.41 96.94 0 top
R61  *EV@Short_0402  [S0402]  87.95 97.01 180 top
R62  *Short_0402  [S0402]  57.97 96.89 270 top
R63  *0_5%_4  [R0402]  58.94 96.86 90 top
R64  EV@100K_1%_4  [R0402]  98.74 96.63 90 top
R65  1.8K_1%_2  [R0201]  44.61 96.51 90 top
R66  39_1%_2  [R0201]  29.6 94.94 270 top
R67  39_1%_2  [R0201]  30.57 94.94 270 top
R68  39_1%_2  [R0201]  31.53 94.94 270 top
R69  39_1%_2  [R0201]  32.5 94.94 270 top
R70  39_1%_2  [R0201]  33.46 94.94 270 top
R71  39_1%_2  [R0201]  34.43 94.94 270 top
R72  39_1%_2  [R0201]  35.39 94.94 270 top
R73  39_1%_2  [R0201]  36.36 94.94 270 top
R74  39_1%_2  [R0201]  37.32 94.94 270 top
R75  39_1%_2  [R0201]  38.29 94.94 270 top
R76  39_1%_2  [R0201]  39.25 94.9 270 top
R77  39_1%_2  [R0201]  40.22 94.94 270 top
R78  39_1%_2  [R0201]  41.18 94.94 270 top
R79  39_1%_2  [R0201]  42.15 94.94 270 top
R80  39_1%_2  [R0201]  43.11 94.94 270 top
R81  *EV@Short_0402  [S0402]  90.18 95.01 270 top
R82  EV@40.2_1%_2  [R0201]  120.04 94.83 180 top
R83  EV@10K_5%_4  [R0402]  85.79 94.73 270 top
R84  EV@40.2_1%_2  [R0201]  120.04 93.81 180 top
R85  39_1%_2  [R0201]  30.45 93.71 0 top
R86  EV@10K_1%_4  [R0402]  90.18 93.1 90 top
R87  39_1%_2  [R0201]  30.45 92.75 0 top
R88  39_1%_2  [R0201]  30.45 91.78 0 top
R89  39_1%_2  [R0201]  30.45 90.82 0 top
R90  39_1%_2  [R0201]  30.45 89.85 0 top
R91  39_1%_2  [R0201]  30.45 88.89 0 top
R92  39_1%_2  [R0201]  30.45 87.92 0 top
R93  20K_1%_2  [R0201]  15.09 86.98 0 top
R94  39_1%_2  [R0201]  29.44 86.9 180 top
R95  39_1%_2  [R0201]  29.44 85.94 180 top
R96  HDMI_N@1M_5%_2  [R0201]  18.1 85.33 180 top
R97  *Short_0402  [S0402]  20 85.33 0 top
R98  *Short_0402  [S0402]  14.92 84.95 0 top
R99  0_5%_4  [R0402]  29.53 84.95 180 top
R100  *10K_5%_4  [R0402]  23.05 84.31 90 top
R101  39_1%_2  [R0201]  29.69 83.96 0 top
R102  0_5%_4  [R0402]  16.7 83.81 270 top
R103  *10K_5%_4  [R0402]  17.71 83.81 270 top
R104  HDMI_R@10.5K_1%_2  [R0201]  20.89 83.64 90 top
R105  0_5%_4  [R0402]  21.91 83.81 270 top
R106  2.2K_5%_2  [R0201]  18.73 83.64 270 top
R107  2.2K_5%_2  [R0201]  19.75 83.64 270 top
R108  39_1%_2  [R0201]  29.69 82.99 0 top
R109  39_1%_2  [R0201]  29.69 82.03 0 top
R110  HDMI_N@0_5%_2  [R0201]  26.22 81.77 0 top
R111  HDMI_N@470_1%_2  [R0201]  13.94 81.39 180 top
R112  49.9_1%_2  [R0201]  32.48 81.27 180 top
R113  240_1%_2  [R0201]  43.15 81.27 180 top
R114  0_5%_4  [R0402]  44.89 81.27 0 top
R115  HDMI_R@0_5%_2  [R0201]  15.56 81.16 180 top
R116  HDMI_N@0_5%_2  [R0201]  26.22 80.63 0 top
R117  HDMI_N@470_1%_2  [R0201]  13.94 80.38 180 top
R118  HDMI_R@0_5%_2  [R0201]  15.56 79.97 180 top
R119  HDMI_N@0_5%_2  [R0201]  26.22 79.87 0 top
R120  0_5%_4  [R0402]  28.43 79.49 270 top
R121  HDMI_N@470_1%_2  [R0201]  13.94 79.36 180 top
R122  HDMI_R@0_5%_2  [R0201]  15.56 79.26 180 top
R123  HDMI_N@0_5%_2  [R0201]  26.22 78.73 0 top
R124  HDMI_N@470_1%_2  [R0201]  13.94 78.35 180 top
R125  *1K_5%_2  [R0201]  93.79 78.22 90 top
R126  1K_5%_2  [R0201]  94.55 78.22 270 top
R127  10K_1%_2  [R0201]  95.31 78.22 270 top
R128  *51_1%_2  [R0201]  100.37 78.22 0 top
R129  *51_1%_2  [R0201]  102.42 78.09 0 top
R130  HDMI_R@0_5%_2  [R0201]  15.56 78.07 180 top
R131  HDMI_N@0_5%_2  [R0201]  26.22 77.96 0 top
R132  *1K_5%_2  [R0201]  104.71 77.96 0 top
R133  1K_5%_2  [R0201]  106.11 77.96 180 top
R134  10K_1%_2  [R0201]  96.07 77.58 270 top
R135  10K_1%_2  [R0201]  96.84 77.58 270 top
R136  10K_1%_2  [R0201]  97.6 77.58 270 top
R137  HDMI_R@0_5%_2  [R0201]  15.56 77.35 180 top
R138  HDMI_N@470_1%_2  [R0201]  13.94 77.33 180 top
R139  *39_1%_4  [R0402]  28.43 77.33 270 top
R140  *1K_5%_2  [R0201]  104.71 77.25 0 top
R141  1K_5%_2  [R0201]  106.11 77.25 180 top
R142  HDMI_N@0_5%_2  [R0201]  26.22 76.82 0 top
R143  51_1%_2  [R0201]  98.92 76.8 270 top
R144  HDMI_N@470_1%_2  [R0201]  13.94 76.31 180 top
R145  HDMI_R@0_5%_2  [R0201]  15.56 76.16 180 top
R146  *1K_5%_2  [R0201]  104.71 76.11 0 top
R147  *10K_1%_2  [R0201]  106.11 76.11 180 top
R148  HDMI_N@0_5%_2  [R0201]  26.22 76.06 0 top
R149  1K_1%_4  [R0402]  60.23 75.75 90 top
R150  HDMI_R@0_5%_2  [R0201]  15.56 75.45 180 top
R151  *1K_5%_2  [R0201]  104.71 75.35 0 top
R152  *10K_1%_2  [R0201]  106.11 75.35 180 top
R153  HDMI_N@470_1%_2  [R0201]  13.94 75.3 180 top
R154  24.9_1%_4  [R0402]  63.56 75.04 0 top
R155  HDMI_N@0_5%_2  [R0201]  26.22 74.92 0 top
R156  51_1%_2  [R0201]  97.27 74.89 180 top
R157  HDMI_N@470_1%_2  [R0201]  13.94 74.28 180 top
R158  1K_1%_4  [R0402]  59.12 74.28 90 top
R159  2_1%_6  [R0603]  61.53 74.28 270 top
R160  HDMI_R@0_5%_2  [R0201]  15.56 74.26 180 top
R161  *1K_5%_2  [R0201]  104.68 74.23 0 top
R162  *10K_1%_2  [R0201]  106.11 74.23 180 top
R163  2.2K_5%_2  [R0201]  20.25 74.15 90 top
R164  2.2K_5%_2  [R0201]  22.24 73.65 90 top
R165  0_5%_4  [R0402]  30.21 73.65 180 top
R166  1K_5%_2  [R0201]  104.68 73.52 0 top
R167  *10K_1%_2  [R0201]  106.11 73.52 180 top
R168  *1K_5%_2  [R0201]  104.68 72.73 0 top
R169  1K_5%_2  [R0201]  106.11 72.73 180 top
R170  0_5%_2  [R0201]  103.8 72 90 top
R171  *1K_5%_2  [R0201]  104.68 72 0 top
R172  1K_5%_2  [R0201]  106.11 72 180 top
R173  49.9_1%_2  [R0201]  102.2 71.51 270 top
R174  *1K_5%_2  [R0201]  104.71 70.85 0 top
R175  *EV@Short_0402  [S0402]  142.43 70.85 90 top
R176  *10K_1%_2  [R0201]  106.11 70.8 180 top
R177  *1K_5%_2  [R0201]  104.71 70.14 0 top
R178  0_5%_6  [R0603]  82.87 70.1 180 top
R179  *10K_1%_2  [R0201]  106.11 70.09 180 top
R180  *10K_1%_2  [R0201]  105.85 69.2 180 top
R181  *1K_5%_2  [R0201]  104.33 69.02 0 top
R182  1K_5%_2  [R0201]  106.74 68.82 270 top
R183  *10K_1%_2  [R0201]  107.5 68.82 270 top
R184  *10K_1%_2  [R0201]  108.27 68.82 270 top
R185  1K_5%_2  [R0201]  105.85 68.44 180 top
R186  *1K_5%_2  [R0201]  104.58 68.31 0 top
R187  *100K_1%_4  [R0402]  109.41 68.06 90 top
R188  1K/F_4  [R0402]  110.81 68.06 90 top
R189  240_1%_2  [R0201]  42.01 67.93 180 top
R190  0_5%_4  [R0402]  43.62 67.93 0 top
R191  *1K_5%_2  [R0201]  107.5 67.8 270 top
R192  *1K_5%_2  [R0201]  108.27 67.8 270 top
R193  *1K_5%_2  [R0201]  105.85 67.68 180 top
R194  *short_4  [S0402]  25.97 64.5 270 top
R195  *short_4  [S0402]  25.97 62.72 90 top
R196  1K/F_4  [R0402]  111.31 62.72 0 top
R197  *0_5%_2  [R0201]  92.09 59.4 270 top
R198  *Short_0402  [S0402]  23.94 58.66 180 top
R199  *0_5%_2  [R0201]  92.06 58.38 90 top
R200  *Short_0402  [S0402]  23.94 57.64 180 top
R201  240_1%_2  [R0201]  50.72 55.68 0 top
R202  *Short_0402  [S0402]  21.93 55.36 180 top
R203  240_1%_2  [R0201]  50.72 54.88 0 top
R204  *Short_0402  [S0402]  21.93 54.34 180 top
R205  240_1%_2  [R0201]  50.72 54.08 180 top
R206  240_1%_2  [R0201]  56.07 53.86 90 top
R207  240_1%_2  [R0201]  54.39 53.68 90 top
R208  240_1%_2  [R0201]  50.72 53.28 180 top
R209  0_5%_4  [R0402]  30.16 52.95 180 top
R210  TPC@0_5%_2  [R0201]  20.89 52.69 0 top
R211  TPC_N@0_5%_2  [R0201]  21.34 52.69 180 top
R212  240_1%_2  [R0201]  50.73 52.56 0 top
R213  240_1%_2  [R0201]  55.43 52.5 90 top
R214  0_5%_6  [R0603]  80.58 51.93 90 top
R215  0_5%_8  [R0805]  61.02 51.85 180 top
R216  240_1%_2  [R0201]  50.73 51.8 0 top
R217  TPC@0_5%_2  [R0201]  20.89 51.55 0 top
R218  TPC_N@0_5%_2  [R0201]  21.34 51.55 180 top
R219  0_5%_6  [R0603]  108.16 51.22 90 top
R220  240_1%_2  [R0201]  55.48 50.99 90 top
R221  *0_5%_6  [R0603]  63.97 50.53 180 top
R222  TPC@10K_5%_4  [R0402]  23.94 49.9 0 top
R223  TPC@39K_1%_2  [R0201]  16.7 49.01 270 top
R224  *10K_5%_4  [R0402]  214.82 49.01 180 top
R225  TPC@10K_5%_4  [R0402]  23.94 48.88 0 top
R226  200_1%_2  [R0201]  80.58 48.83 0 top
R227  4.7K_5%_2  [R0201]  213.09 48.63 0 top
R228  240_1%_2  [R0201]  40.99 48.12 180 top
R229  0_5%_4  [R0402]  42.61 48.12 0 top
R230  49.9_1%_2  [R0201]  80.07 47.81 180 top
R231  10_5%_2  [R0201]  66.36 47.76 180 top
R232  62_1%_4  [R0402]  213.55 47.66 0 top
R233  10_5%_2  [R0201]  65.34 47.53 180 top
R234  TPC@100K_5%_4  [R0402]  23.56 47.36 90 top
R235  TPC@20K_1%_2  [R0201]  16.7 47.23 90 top
R236  10_5%_2  [R0201]  66.36 47 180 top
R237  10_5%_2  [R0201]  65.34 46.72 180 top
R238  62_1%_4  [R0402]  213.55 46.62 0 top
R239  100K_5%_2  [R0201]  62.55 46.44 270 top
R240  49.9_1%_2  [R0201]  66.36 46.24 180 top
R241  *100K_5%_2  [R0201]  80.83 46.01 0 top
